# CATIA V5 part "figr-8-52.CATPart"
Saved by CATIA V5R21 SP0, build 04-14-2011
Part number: Part1
Bounding box of the stored display mesh (mm): x -37.5 to 37.5, y -150 to 150, z 0 to 10
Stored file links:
  D:\CATIA V5R21 E-RESOURCES\CATIA-V5R21\catia-v5r21-prt\c08-catia-v5r20-prt\c08-catia-v5r21-figr-8-52.CATPart
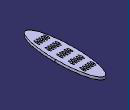
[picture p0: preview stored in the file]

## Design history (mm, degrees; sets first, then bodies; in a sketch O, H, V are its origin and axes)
Body1 (main body)
  Sketch1 on xy-plane, origin (0, 0, 0), H (1, 0, 0), V (0, 1, 0)
    circle A1 centre (0, 0) radius 75
    point P1 (0, 75)
    radius A1 = 75
    coincidence: A1 P1, P1 V
  Pad1: profile Sketch1, direction (0, 0, 1), length 10
  Sketch2 on face of Pad1, origin (0, 0, 10), H (1, 0, 0), V (0, 1, 0)
    circle A1 centre (35, -45) radius 6
    point P1 (35, -45)
    distance P1 H = 45
    distance V P1 = 35
    radius A1 = 6
  Pocket1: profile Sketch2, direction (0, 0, -1), through (limit type 3)
  RectPattern1: of Pocket1, direction 1 instances 5, spacing 19, along xy-plane reversed, direction 2 instances 5, spacing 22, along xy-plane
  Affinity1: ToTransfor RectPattern1, RatioX 0.5, RatioY 2, RatioZ 1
